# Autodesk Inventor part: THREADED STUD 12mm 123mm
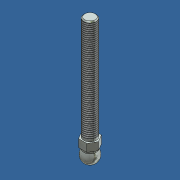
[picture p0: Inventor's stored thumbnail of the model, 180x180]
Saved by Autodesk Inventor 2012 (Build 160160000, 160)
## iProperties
Created: 2007-03
Part Number: THREADED STUD 12mm 123mm
Document SubType Name: Modeling
Designer: Andy Moles
Material: Steel
Mass: 156.787 g
Surface Area: 68.4363 cm^2
Volume: 19.9729 cm^3
Density: 7.85 g/cm^3
Author: Andy Moles
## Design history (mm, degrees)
sketch "Sketch1"
  geometry: L1 (0, -7.5)-(0, 7.5); A1 r 7.5 centre (0, 0) between (0, -7.5) and (0, 7.5); 1 further point
  constraints: 2 end point, 2 point on circle, 1 centre point, 1 coincident, 1 midpoint, 1 vertical
  dimensions: "d5" = 15 distance of L1.start L1.end
revolve "Revolution1" sketch "Sketch1" stored, may be unused: angle "d1" = 90 deg
sketch "Sketch2"
  geometry: C1 r 6 at (0, 0); 1 further point
  constraints: 1 centre point, 1 coincident
  dimensions: "d2" = 12 diameter of C1
extrude "Extrusion1" join sketch "Sketch2" distance "d3" = 7; taper "d4" = 0 deg
sketch "Sketch3"
  geometry: L1 (-4.041, 7)-(4.041, 7); L2 (4.041, 7)-(8.083, 0); L3 (8.083, 0)-(4.041, -7); L4 (4.041, -7)-(-4.041, -7); L5 (-4.041, -7)-(-8.083, 0); L6 (-8.083, 0)-(-4.041, 7); C1 r 6 at (0, 0) reference; 1 further point
  constraints: 12 end point, 5 equal length, 1 horizontal, 1 horizontal alignment, 1 midpoint, 1 parallel, 1 vertical alignment
  dimensions: "d6" = 120 deg angle of L6 L5; "d7" = 120 deg angle of L1 L6; "d8" = 14 distance between parallel lines of L4 L1
extrude "Extrusion2" join sketch "Sketch3" distance "d9" = 7.5; taper "d10" = 0 deg
sketch "Sketch4"
  geometry: C1 r 6 at (0, 0); 1 further point
  constraints: 1 centre point, 1 coincident
  dimensions: "d11" = 12 diameter of C1
extrude "Extrusion3" join sketch "Sketch4" distance "d12" = 100; taper "d13" = 0 deg
thread "Thread1" dims "d14" = 147, "d15" = 2
chamfer "Chamfer1" distance "d16" = 1; stored, may be unused: second distance "d17" = 2, angle "d18" = 45 deg
body "Solid1"
